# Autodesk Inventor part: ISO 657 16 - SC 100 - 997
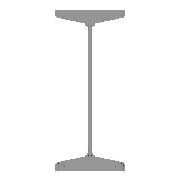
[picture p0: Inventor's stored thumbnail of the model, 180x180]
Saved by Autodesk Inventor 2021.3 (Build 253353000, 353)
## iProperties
Created: 2018-07
Part Number: ISO 657 16 - SC 100 - 997
Material: Acier, doux
Description: Poutres en acier laminées à chaud - Partie 16: profilés en H (série métrique) - Cotes et propriétés de section
Document SubType Name: Modeling
Standard: ISO
Designer: Fabian Perrée
Standard Revision: First edition 1980-02-15
Standards Organization: ISO
Language: fr-FR
Size Designation: SC 100
Categories: <MemberInstance><Categories><Category DisplayName="Profilés" InternalName="089c4875-fa83-4c05-b084-43b9cc11f5ed" Mnemonic="GRDR"><CategoryParameter DisplayName=
Stock Number: SC 100
Density: 7.85 g/cm^3
Appearance: Semi-poli
Mass: 19823.1 g
Surface Area: 5410.82 cm^2
Volume: 2525.23 cm^3
_CCFamilyMember: 1
_CCFamilyDisplayName: ISO 657/16 - 1980 - Poutres en acier laminées à chaud - Partie 16: profilés en H (série métrique) - Cotes et propriétés de section
_FrameMemberDoc: Frame Member File
_Version: 25.0.0
_GetPNFromCC: 1
G_W: 100,000 mm
G_H: 100,000 mm
+66B73B83-1ABF-4F18-8224-AF9602477DE0+DETAILDECOUPE1: Grugeage
G_L: 997,000 mm
IsCustomPart: 1
Author: Fabian Perrée
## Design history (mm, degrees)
node "Plan de départ"
node "Plan de fin"
sketch "Esquisse"
  geometry: L1 (-3, 0)-(-3, -26.266); L2 (-13.33, -38.149)-(-44.835, -42.577); L3 (-50, -48.518)-(-50, -50); L4 (-50, -50)-(0, -50); L5 (-26.5, -50)-(-26.5, -40); L6 (-61.333, 0)-(81.777, 0); L7 (0, 0)-(0, -50); L8 (0, -60)-(0, 80); L9 (3, 0)-(3, -26.266); L10 (13.33, -38.149)-(44.835, -42.577); L11 (50, -48.518)-(50, -50); L12 (50, -50)-(0, -50); L13 (-3, 0)-(0, 0); L14 (-3, 0)-(-3, 26.266); L15 (-13.33, 38.149)-(-44.835, 42.577); L16 (-50, 48.518)-(-50, 50); L17 (-50, 50)-(0, 50); L18 (50, 48.518)-(50, 50); L19 (13.33, 38.149)-(44.835, 42.577); L20 (3, 0)-(3, 26.266); L21 (50, 50)-(0, 50); L22 (0, 108)-(0, -88) reference; L23 (-89.955, 0)-(110.399, 0) reference; A1 r 6 centre (-44, 48.518) between (-50, 48.518) and (-44.835, 42.577); A2 r 6 centre (44, 48.518) between (44.835, 42.577) and (50, 48.518); A3 r 6 centre (44, -48.518) between (50, -48.518) and (44.835, -42.577); A4 r 6 centre (-44, -48.518) between (-44.835, -42.577) and (-50, -48.518); A5 r 12 centre (-15, 26.266) between (-3, 26.266) and (-13.33, 38.149); A6 r 12 centre (15, 26.266) between (13.33, 38.149) and (3, 26.266); A7 r 12 centre (15, -26.266) between (3, -26.266) and (13.33, -38.149); A8 r 12 centre (-15, -26.266) between (-13.33, -38.149) and (-3, -26.266); 14 further points
  constraints: 42 end point, 24 point on line, 17 symmetric about line, 16 point on circle, 16 tangent, 8 centre point, 6 equal radius, 4 collinear, 2 perpendicular, 12 other
  dimensions: "d1" = 10 vertical distance of L3.end L5.end (= G_T1); "d2" = 23.5 distance between parallel lines of L5 L3 (= -0.25 x G_T + 0.25 x G_W); "d3" = 3 distance between parallel lines of L1 L7 (= 0.5 x G_T); "d4" = 50 distance between parallel lines of L7 L3 (= 0.5 x G_W); "d9" = 50 distance from line of L1.start L4 (= 0.5 x G_H); "d14" = 98 deg angle of L2 L1 (= G_NG); "d15" = 6 radius of A1 (= G_ER); "d16" = 12 radius of A5 (= G_IR)
extrude "Corps" new body sketch "Esquisse" stored distance "d5" = 997 (= G_L); taper "d6" = 0 deg
node "Driven Length"
  sketch "Sketch3"
    geometry: L1 (0, 0)-(10, 0) reference
    constraints: 2 end point, 1 horizontal
  workplane "Work Plane3"
  sketch "Sketch4"
    geometry: L1 (-2, 0)-(12, 0) reference; L2 (-2, 1000)-(12, 1000) reference
    dimensions: "d20" = 1000 distance between parallel lines of L1 L2 (derived)
node "Plan de construction4"
node "Plan de construction5"
node "Plan de construction6"
sketch "Esquisse5"
  geometry: L1 (-3, 0)-(-3, -26.266); L2 (-13.33, -38.149)-(-44.835, -42.577); L3 (-50, -48.518)-(-50, -50); L4 (-50, -50)-(0, -50); L5 (50, -50)-(0, -50); L6 (50, -48.518)-(50, -50); L7 (13.33, -38.149)-(44.835, -42.577); L8 (3, 0)-(3, -26.266); L9 (3, 0)-(3, 26.266); L10 (13.33, 38.149)-(44.835, 42.577); L11 (50, 48.518)-(50, 50); L12 (50, 50)-(0, 50); L13 (-50, 50)-(0, 50); L14 (-50, 48.518)-(-50, 50); L15 (-13.33, 38.149)-(-44.835, 42.577); L16 (-3, 0)-(-3, 26.266); A1 r 12 centre (-15, -26.266) between (-13.33, -38.149) and (-3, -26.266); A2 r 6 centre (-44, -48.518) between (-44.835, -42.577) and (-50, -48.518); A3 r 6 centre (44, -48.518) between (50, -48.518) and (44.835, -42.577); A4 r 12 centre (15, -26.266) between (3, -26.266) and (13.33, -38.149); A5 r 12 centre (15, 26.266) between (13.33, 38.149) and (3, 26.266); A6 r 6 centre (44, 48.518) between (44.835, 42.577) and (50, 48.518); A7 r 6 centre (-44, 48.518) between (-50, 48.518) and (-44.835, 42.577); A8 r 12 centre (-15, 26.266) between (-3, 26.266) and (-13.33, 38.149)
  constraints: 32 end point, 16 point on circle, 8 centre point
extrude "Extrusion2" cut sketch "Esquisse5" stored distance "d21" = 0.13; taper "d22" = 0 deg
body "Solid1"
other parameters: "G_W" = 100 (= G_H) [user parameter; used in 2 equation terms], "G_H" = 100 [user parameter; used in 2 equation terms], "G_T" = 6 [user parameter; used in 2 equation terms], "G_T1" = 10 [user parameter; used in 1 equation term], "G_L" = 997 [user parameter; used in 1 equation term], "G_ER" = 6 [user parameter; used in 1 equation term], "G_IR" = 12 [user parameter; used in 1 equation term], "G_NG" = 98 deg [user parameter; used in 1 equation term], "G_OFFSET_START" = 0 [user parameter; used in 1 equation term], "G_OFFSET_END" = 0 [user parameter; used in 1 equation term], "d17" = 0 (computed from G_OFFSET_START), "d19" = 90 deg
